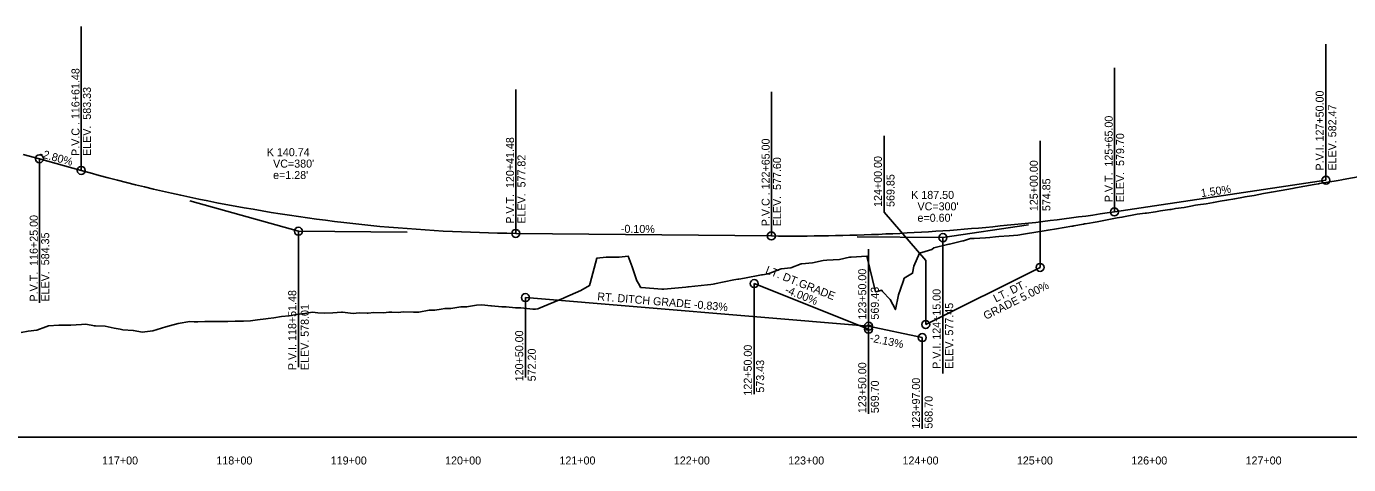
# Model space of a CAD drawing. Extents: x 634057 to 641016, y 287858 to 292331.
# Drawn here: x 639229 to 640386, y 288821 to 289205 of the extents above; entities that cross this region are included whole.
import ezdxf

# ---------------------------------------------------------------- set-up
doc = ezdxf.new("R2010")
doc.units = 0
for name, color, linetype in [('R_Axis', 7, 'Continuous'), ('R_Axis Annot', 7, 'Continuous'), ('R_No Plot', 7, 'Continuous'), ('R_Vert Alg', 7, 'Continuous'), ('R_Vert Alg Annot', 7, 'Continuous')]:
    doc.layers.add(name, color=color, linetype=linetype)

msp = doc.modelspace()

# ---------------------------------------------------------------- linework, layer by layer
at = {"layer": 'R_Axis'}
msp.add_line((637415.8, 288845.5), (640715.8, 288845.5), dxfattribs=at)
at = {"layer": 'R_No Plot'}
msp.add_lwpolyline([(639224.8, 288937.1), (639231, 288938.2), (639238.4, 288939), (639246.4, 288942), (639248.7, 288942.9), (639257.8, 288943.5), (639268.1, 288943.5), (639268.3, 288943.5), (639277.6, 288944.1), (639281.3, 288944.3), (639288.8, 288942.8), (639289.7, 288942.7), (639298.2, 288942.4), (639306, 288940.8), (639311.3, 288939.8), (639313.8, 288939.3), (639322.8, 288938.8), (639330.9, 288937.2), (639332.9, 288937.5), (639339.8, 288938.6), (639351.4, 288941.9), (639354.5, 288942.8), (639362, 288944.9), (639372.3, 288946.5), (639376.1, 288946.4), (639379.4, 288946.4), (639385.5, 288946.6), (639392.5, 288946.5), (639397.7, 288946.7), (639398.8, 288946.7), (639405.6, 288946.7), (639412, 288946.9), (639418.7, 288946.9), (639419.3, 288946.9), (639425.2, 288947.1), (639431.6, 288948.2), (639438.8, 288949), (639440.9, 288949.2), (639445.6, 288949.7), (639452.4, 288950.9), (639459.2, 288951.7), (639462.5, 288952.2), (639466, 288952.8), (639472.8, 288953.6), (639479.6, 288954.8), (639484.1, 288954.3), (639490.4, 288953.8), (639497.3, 288954.3), (639504.8, 288954.8), (639505.8, 288954.7), (639515.2, 288953.6), (639520.4, 288954.3), (639527.4, 288954), (639528.3, 288954), (639533.3, 288954.6), (639541.5, 288954.3), (639546.2, 288954.9), (639549, 288954.8), (639554.6, 288954.6), (639559.1, 288955.1), (639567.8, 288954.8), (639570.6, 288954.8), (639572.6, 288954.8), (639581.6, 288956.4), (639586.5, 288956.4), (639592.2, 288957.4), (639595.4, 288957.9), (639600.4, 288957.9), (639609.2, 288959.4), (639613.8, 288959.4), (639614.3, 288959.4), (639623, 288960.9), (639627.7, 288961.1), (639635.4, 288960.3), (639636, 288960.3), (639645.1, 288959.4), (639648.9, 288959.5), (639657, 288958.7), (639658.7, 288958.5), (639661.7, 288958.6), (639672.2, 288957.5), (639674.6, 288957.5), (639676.6, 288957.7), (639678.6, 288958.6), (639697.6, 288966.6), (639698.5, 288966.8), (639700.2, 288967.6), (639714.3, 288973.7), (639721.7, 288978), (639721.8, 288978), (639721.9, 288978.2), (639722.4, 288980.2), (639728.2, 289002.1), (639736.5, 289003), (639743.5, 289002.9), (639747.7, 289002.8), (639755.6, 289003.7), (639759, 288994.4), (639763.3, 288982.1), (639765.1, 288978.9), (639766.5, 288976.4), (639767.4, 288976.4), (639784.9, 288974.8), (639785.5, 288974.9), (639786.1, 288974.9), (639786.7, 288975), (639806, 288976.8), (639807.7, 288977), (639808.3, 288977), (639825.1, 288978.7), (639827.9, 288979.1), (639829.9, 288979.4), (639831.1, 288979.5), (639848, 288983), (639851.5, 288983.6), (639852.4, 288983.7), (639857.2, 288984.4), (639872.2, 288987.5), (639873.1, 288987.6), (639878, 288988.4), (639889.3, 288992.8), (639897.7, 288993.7), (639907, 288997), (639907.6, 288997.1), (639916.7, 288997.9), (639926.2, 288999.9), (639929.2, 289000.2), (639940.5, 289001), (639949.2, 289002.8), (639950.7, 289002.9), (639964.4, 289003.8), (639972, 288972.6), (639972.2, 288972.7), (639977.4, 288973.9), (639977.9, 288973), (639984.6, 288966), (639989.3, 288957.1), (639992.1, 288970.1), (639993.7, 288974.9), (639996.3, 288982.5), (639997, 288984.5), (640004.3, 288988.8), (640005.4, 288995), (640010.4, 289006.5), (640015.2, 289007.9), (640021, 289009.5), (640023, 289011.2), (640034.7, 289014), (640035.9, 289014.2), (640036.7, 289014.4), (640048.3, 289017.2), (640048.8, 289017.3), (640054.9, 289019.2), (640058.2, 289019.3), (640068, 289019.8), (640071.9, 289020.2), (640076.7, 289020.7), (640079.7, 289020.9), (640088.9, 289021.6), (640096.4, 289022.3), (640101.3, 289023), (640103, 289023.3), (640121, 289026.3), (640122.7, 289026.5), (640122.8, 289026.6), (640130.1, 289027.8), (640143.7, 289030), (640144.3, 289030.1), (640145.4, 289030.3), (640153.7, 289031.9), (640154.6, 289032), (640155.2, 289032.2), (640158.9, 289032.7), (640162.2, 289033.2), (640165.8, 289033.9), (640183.3, 289037.2), (640187.3, 289037.9), (640200.8, 289040.5), (640207.8, 289041.4), (640208.8, 289041.5), (640216.6, 289042.6), (640221.1, 289043.4), (640229.2, 289044.5), (640230.3, 289044.7), (640234.3, 289045.4), (640241.9, 289046.5), (640247.6, 289047.5), (640251.8, 289048.3), (640253.8, 289048.6), (640260.9, 289049.6), (640267.4, 289050.8), (640273.4, 289051.8), (640278.9, 289052.7), (640286, 289054), (640293.7, 289055.4), (640294.9, 289055.6), (640303, 289057), (640311.2, 289058.5), (640316.4, 289059.4), (640318.1, 289059.8), (640333.4, 289062.5), (640337.9, 289063.4), (640339.1, 289063.6), (640355.6, 289066.6), (640359.4, 289067.2), (640360, 289067.3), (640376.5, 289070.1), (640379.8, 289070.7), (640380.9, 289070.9), (640397.2, 289073.7)], dxfattribs=at)
at = {"layer": 'R_Vert Alg'}
for p, q in [((639277.3, 289078.8), (639277.3, 289204.8)), ((640365.8, 289070.2), (640365.8, 289189.2)), ((640180.8, 289042.5), (640180.8, 289168.5)), ((639657.3, 289023.7), (639657.3, 289149.7)), ((639880.8, 289021.5), (639880.8, 289147.5)), ((639979.5, 289042.2), (639979.5, 289109.2)), ((640115.8, 288994), (640115.8, 289104.7)), ((639240.8, 289089), (639240.8, 288963)), ((639240.8, 289089), (639277.3, 289078.8)), ((640180.8, 289042.5), (640365.8, 289070.2)), ((639372.3, 289052.2), (639467.3, 289025.6)), ((639467.3, 289025.6), (639562.3, 289024.7)), ((639467.3, 289025.6), (639467.3, 288906.6)), ((640030.8, 289020), (640105.8, 289031.2)), ((639657.3, 289023.7), (639880.8, 289021.5)), ((639955.8, 289020.7), (640030.8, 289020)), ((640030.8, 289020), (640030.8, 288901)), ((639965.8, 288939.8), (639965.8, 289009.8)), ((640015.8, 288944), (640015.8, 289000)), ((640015.8, 288944), (640115.8, 288994)), ((639865.8, 288883), (639865.8, 288979.8)), ((639865.8, 288979.8), (639965.8, 288939.8)), ((639665.8, 288897.5), (639665.8, 288967.5)), ((639665.8, 288967.5), (639965.8, 288942.5)), ((639965.8, 288865.7), (639965.8, 288942.5)), ((639965.8, 288942.5), (640012.8, 288932.5)), ((640012.8, 288852.7), (640012.8, 288932.5))]:
    msp.add_line(p, q, dxfattribs=at)
for points in [[(639226.6, 289092.9), (639240.8, 289089)], [(639277.3, 289078.8), (639285.2, 289076.6), (639293.1, 289074.5), (639301, 289072.4), (639308.9, 289070.3), (639316.9, 289068.3), (639324.8, 289066.3), (639332.7, 289064.4), (639340.6, 289062.5), (639348.5, 289060.7), (639356.4, 289058.9), (639364.4, 289057.1), (639372.3, 289055.4), (639380.2, 289053.8), (639388.1, 289052.2), (639396, 289050.6), (639403.9, 289049.1), (639411.9, 289047.6), (639419.8, 289046.1), (639427.7, 289044.8), (639435.6, 289043.4), (639443.5, 289042.1), (639451.4, 289040.8), (639459.4, 289039.6), (639475.2, 289037.3), (639483.1, 289036.3), (639491, 289035.2), (639498.9, 289034.2), (639506.9, 289033.3), (639514.8, 289032.4), (639522.7, 289031.5), (639530.6, 289030.7), (639538.5, 289029.9), (639546.4, 289029.2), (639554.4, 289028.5), (639562.3, 289027.9), (639570.2, 289027.3), (639578.1, 289026.8), (639586, 289026.2), (639593.9, 289025.8), (639601.9, 289025.4), (639609.8, 289025), (639617.7, 289024.7), (639625.6, 289024.4), (639633.5, 289024.2), (639641.4, 289024), (639649.4, 289023.8), (639657.3, 289023.7)], [(639880.8, 289021.5), (639887, 289021.4), (639893.3, 289021.4), (639899.5, 289021.4), (639905.8, 289021.4), (639912, 289021.4), (639918.3, 289021.5), (639924.5, 289021.6), (639930.8, 289021.7), (639937, 289021.8), (639943.3, 289021.9), (639949.5, 289022.1), (639955.8, 289022.2), (639962, 289022.4), (639968.3, 289022.7), (639974.5, 289022.9), (639980.8, 289023.2), (639987, 289023.4), (639993.3, 289023.7), (639999.5, 289024.1), (640005.8, 289024.4), (640012, 289024.8), (640018.3, 289025.2), (640024.5, 289025.6), (640037, 289026.4), (640043.3, 289026.9), (640049.5, 289027.4), (640055.8, 289027.9), (640062, 289028.4), (640068.3, 289029), (640074.5, 289029.6), (640080.8, 289030.2), (640087, 289030.8), (640093.3, 289031.4), (640099.5, 289032.1), (640105.8, 289032.7), (640112, 289033.4), (640118.3, 289034.2), (640124.5, 289034.9), (640130.8, 289035.7), (640137, 289036.4), (640143.3, 289037.2), (640149.5, 289038.1), (640155.8, 289038.9), (640162, 289039.8), (640168.3, 289040.7), (640174.5, 289041.6), (640180.8, 289042.5)], [(639979.5, 289042.2), (640015.8, 289000)]]:
    msp.add_lwpolyline(points, dxfattribs=at)
for centre in [(639240.8, 289089), (639277.3, 289078.8), (640365.8, 289070.2), (640180.8, 289042.5), (639467.3, 289025.6), (639657.3, 289023.7), (639880.8, 289021.5), (640030.8, 289020), (640115.8, 288994), (639865.8, 288979.8), (639665.8, 288967.5), (639965.8, 288942.5), (639965.8, 288939.8), (640015.8, 288944), (640012.8, 288932.5)]:
    msp.add_circle(centre, 3.5, dxfattribs=at)

# ---------------------------------------------------------------- texts
at = {"layer": 'R_Axis Annot'}
for s, p in [('117+00', (639295.5, 288821.5)), ('118+00', (639395.5, 288821.5)), ('119+00', (639495.5, 288821.5)), ('120+00', (639595.5, 288821.5)), ('121+00', (639695.5, 288821.5)), ('122+00', (639795.5, 288821.5)), ('123+00', (639895.5, 288821.5)), ('124+00', (639995.5, 288821.5)), ('125+00', (640095.5, 288821.5)), ('126+00', (640195.5, 288821.5)), ('127+00', (640295.5, 288821.5))]:
    msp.add_text(s, height=7, dxfattribs=at).set_placement(p)
at = {"layer": 'R_Vert Alg Annot'}
for s, rotation, p in [('P.V.C . 116+61.48', 90, (639275.8, 289091.5)), ('ELEV.  583.33', 90, (639285.8, 289091.5)), ('P.V.I. 127+50.00', 90, (640363.8, 289078.7)), ('ELEV. 582.47', 90, (640374.8, 289078.7)), ('P.V.T.  125+65.00', 90, (640179.3, 289051)), ('P.V.T.  120+41.48', 90, (639655.8, 289032.2)), ('P.V.C . 122+65.00', 90, (639879.3, 289030)), ('ELEV.  579.70', 90, (640189.3, 289051)), ('-2.80%', 344.3578, (639240.3, 289090.7)), ('ELEV.  577.82', 90, (639665.8, 289032.2)), ('ELEV.  577.60', 90, (639889.3, 289030)), ('124+00.00', 90, (639977.5, 289046.9)), ('125+00.00', 90, (640113.8, 289043.2)), ('569.85', 90, (639988.5, 289046.9)), ('574.85', 90, (640124.8, 289043.2)), ('1.50%', 8.5308, (640256.9, 289055.4)), ('P.V.T.  116+25.00', 90, (639239.3, 288964.1)), ('-0.10%', 359.4271, (639749.2, 289024.3)), ('ELEV.  584.35', 90, (639249.3, 288964.1)), ('LT. DT.GRADE', 338.1986, (639875.1, 288989.1)), ('123+50.00', 90, (639963.8, 288948.3)), ('GRADE 5.00%', 26.5651, (640068.4, 288948)), ('LT. DT.', 26.5651, (640077.1, 288963.2)), ('P.V.I. 118+51.48', 90, (639465.3, 288904.1)), ('RT. DITCH GRADE -0.83%', 355.2364, (639728.4, 288965.2)), ('-4.00%', 338.1986, (639892.1, 288971.8)), ('569.43', 90, (639974.8, 288948.3)), ('P.V.I. 124+15.00', 90, (640028.8, 288905.2)), ('ELEV. 578.01', 90, (639476.3, 288904.1)), ('ELEV. 577.45', 90, (640039.8, 288905.2)), ('120+50.00', 90, (639663.8, 288894.3)), ('-2.13%', 347.9885, (639966.6, 288929.2)), ('572.20', 90, (639674.8, 288894.3)), ('122+50.00', 90, (639863.7, 288881.8)), ('573.43', 90, (639874.5, 288884.4)), ('123+50.00', 90, (639963.8, 288866.4)), ('123+97.00', 90, (640010.8, 288852.9)), ('569.70', 90, (639974.8, 288866.4)), ('568.70', 90, (640021.8, 288852.9))]:
    msp.add_text(s, height=7, rotation=rotation, dxfattribs=at).set_placement(p)
for s, p in [('K 140.74', (639439.6, 289091.3)), ("VC=380'", (639445.1, 289081.3)), ("e=1.28'", (639445.1, 289071.3)), ('K 187.50', (640003.1, 289053.9)), ("VC=300'", (640008.6, 289043.9)), ("e=0.60'", (640008.6, 289033.9))]:
    msp.add_text(s, height=7, dxfattribs=at).set_placement(p)

doc.saveas('drawing.dxf')
